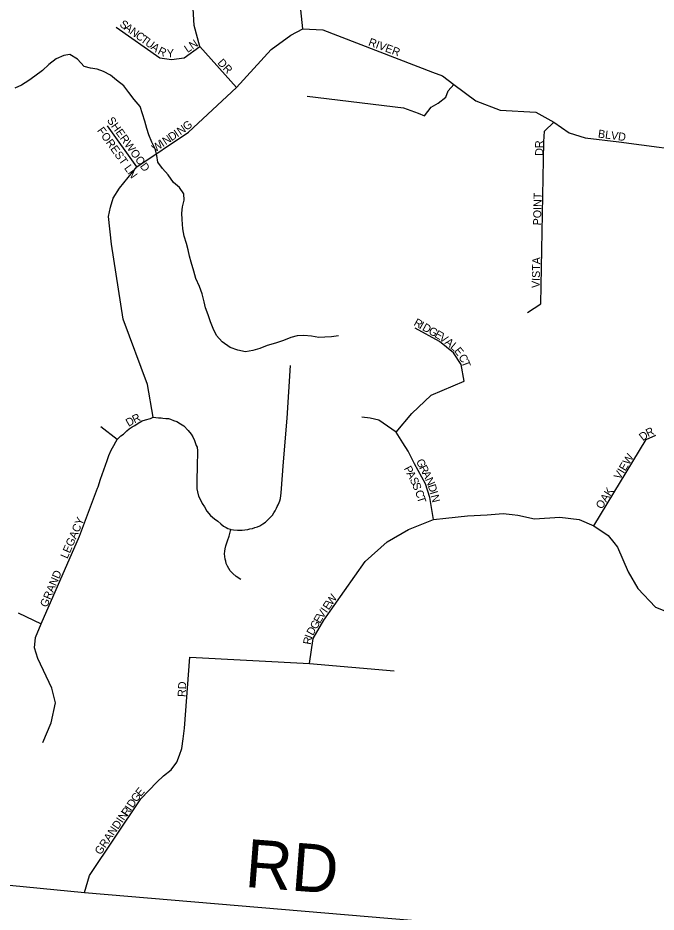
# Model space of a CAD drawing. Extents: x 0 to 1064, y 0 to 440.
# Drawn here: x 216.94 to 229.03, y 141.96 to 158.89 of the extents above; entities that cross this region are included whole.
import ezdxf

# ---------------------------------------------------------------- set-up
doc = ezdxf.new("R2010")
doc.units = 0
for name, color, linetype in [('GM_X_County_Road', 7, 'Continuous'), ('GM_X_County_Road_Text', 7, 'Continuous'), ('GM_X_Minor_River', 7, 'Continuous'), ('GM_X_Township_Road', 7, 'Continuous'), ('GM_X_Township_Subdivision', 7, 'Continuous'), ('GM_X_Township_Subdivision_Text', 7, 'Continuous')]:
    doc.layers.add(name, color=color, linetype=linetype)

msp = doc.modelspace()

# ---------------------------------------------------------------- linework, layer by layer
at = {"layer": 'GM_X_County_Road'}
msp.add_lwpolyline([(210.856, 148.164), (210.902, 148.053), (210.988, 147.945), (211.134, 147.956), (211.385, 148.01), (211.572, 148.026), (211.72, 147.948), (211.782, 147.854), (211.981, 147.333), (212.54, 145.964), (212.819, 145.507), (213.028, 145.15), (213.216, 144.884), (213.897, 144.447), (214.107, 144.144), (215.283, 143.149), (215.934, 142.551), (218.2, 142.332), (231.034, 141.244)], dxfattribs=at)
at = {"layer": 'GM_X_Minor_River'}
msp.add_lwpolyline([(223.009, 152.875), (222.881, 152.852), (222.754, 152.848), (222.638, 152.844), (222.499, 152.864), (222.353, 152.879), (222.231, 152.875), (222.109, 152.84), (221.968, 152.788), (221.816, 152.736), (221.663, 152.689), (221.522, 152.631), (221.388, 152.597), (221.253, 152.568), (221.108, 152.601), (220.957, 152.652), (220.807, 152.758), (220.699, 152.881), (220.641, 153.009), (220.588, 153.138), (220.542, 153.272), (220.495, 153.401), (220.467, 153.516), (220.427, 153.669), (220.381, 153.809), (220.31, 153.962), (220.27, 154.097), (220.224, 154.268), (220.19, 154.384), (220.167, 154.499), (220.133, 154.621), (220.087, 154.762), (220.065, 154.902), (220.049, 155.078), (220.045, 155.194), (220.059, 155.315), (220.086, 155.442), (220.082, 155.564), (219.999, 155.681), (219.885, 155.78), (219.784, 155.921), (219.677, 156.044), (219.593, 156.161), (219.571, 156.289), (219.537, 156.417), (219.478, 156.54), (219.42, 156.68), (219.379, 156.802), (219.345, 156.937), (219.299, 157.077), (219.253, 157.218), (219.139, 157.347), (219.038, 157.482), (218.943, 157.605), (218.805, 157.717), (218.691, 157.81), (218.558, 157.879), (218.438, 157.923), (218.316, 157.943), (218.195, 157.976), (218.07, 158.111), (217.926, 158.199), (217.81, 158.182), (217.663, 158.118), (217.527, 158.011), (217.404, 157.897), (217.262, 157.79), (217.145, 157.707), (217.01, 157.618), (216.881, 157.565)], dxfattribs=at)
at = {"layer": 'GM_X_Township_Road'}
for points in [[(224.643, 157.037), (224.766, 157.202), (224.898, 157.282), (225.047, 157.39), (225.087, 157.515), (225.199, 157.631)], [(222.417, 157.409), (224.24, 157.194), (224.52, 157.093), (224.643, 157.037)]]:
    msp.add_lwpolyline(points, dxfattribs=at)
at = {"layer": 'GM_X_Township_Subdivision'}
for points in [[(221.078, 157.575), (220.388, 158.353), (220.281, 158.753), (220.204, 160.043), (220.184, 160.66), (220.255, 160.969), (220.511, 161.551), (220.74, 161.966)], [(222.339, 158.685), (222.259, 159.415), (222.294, 160.086), (222.497, 160.677), (222.841, 161.172)], [(219.5, 151.332), (219.395, 151.952), (218.936, 153.186), (218.712, 154.611), (218.658, 155.134), (218.692, 155.311), (218.742, 155.483), (218.864, 155.67), (219.194, 156.072), (220.171, 156.733), (221.078, 157.575), (221.736, 158.298), (222.109, 158.57), (222.339, 158.685), (222.712, 158.671), (224.791, 157.868)], [(218.798, 158.717), (219.628, 158.135), (219.849, 158.108), (220.087, 158.135), (220.388, 158.353)], [(224.791, 157.868), (224.981, 157.795), (225.199, 157.631), (225.612, 157.321), (226.074, 157.149), (226.747, 157.106), (227.091, 156.922), (227.382, 156.72), (227.683, 156.624), (228.321, 156.544), (229.947, 156.331), (230.55, 156.371)], [(219.194, 156.072), (218.639, 156.851)], [(226.593, 153.314), (226.841, 153.482), (226.902, 156.546), (226.911, 156.749), (227.091, 156.922)], [(224.104, 151.049), (224.399, 151.402), (224.77, 151.748), (225.39, 152.017), (225.334, 152.332), (225.191, 152.551), (224.924, 152.765), (224.465, 153.018)], [(217.411, 145.169), (217.571, 145.542), (217.651, 145.925), (217.583, 146.2), (217.314, 146.761), (217.251, 146.962), (217.274, 147.162), (217.382, 147.42), (218.104, 149.08), (218.45, 149.991), (218.459, 150.016), (218.505, 150.158), (218.628, 150.514), (218.662, 150.609), (218.707, 150.705), (218.758, 150.797), (218.792, 150.865), (218.819, 150.912), (218.891, 150.982), (218.942, 151.012), (218.97, 151.04), (219.004, 151.077), (219.045, 151.111), (219.103, 151.152), (219.154, 151.176), (219.216, 151.217), (219.291, 151.262), (219.356, 151.282), (219.448, 151.31), (219.5, 151.332), (219.605, 151.323), (219.656, 151.323), (219.687, 151.316), (219.742, 151.31), (219.79, 151.306), (219.827, 151.293), (219.885, 151.272), (219.947, 151.251), (220.018, 151.207), (220.08, 151.166), (220.162, 151.081), (220.223, 151.012), (220.251, 150.961), (220.285, 150.893), (220.319, 150.797), (220.336, 150.766), (220.343, 150.695), (220.333, 150.391), (220.329, 150.145), (220.329, 150.126), (220.326, 150.046), (220.329, 149.974), (220.343, 149.919), (220.363, 149.837), (220.398, 149.769), (220.432, 149.701), (220.476, 149.632), (220.521, 149.554), (220.585, 149.472), (220.661, 149.41), (220.726, 149.362), (220.78, 149.311), (220.831, 149.27), (220.884, 149.245), (220.914, 149.226), (220.958, 149.21), (220.975, 149.206), (221.025, 149.197), (221.099, 149.193), (221.137, 149.193), (221.187, 149.195), (221.238, 149.199), (221.292, 149.203), (221.33, 149.218), (221.385, 149.226), (221.429, 149.241), (221.477, 149.256), (221.52, 149.277), (221.576, 149.313), (221.629, 149.346), (221.675, 149.388), (221.724, 149.441), (221.759, 149.479), (221.789, 149.521), (221.81, 149.561), (221.835, 149.611), (221.852, 149.641), (221.867, 149.67), (221.888, 149.714), (221.9, 149.748), (221.911, 149.79), (221.925, 149.899), (221.972, 150.486), (222.037, 151.317), (222.104, 152.309)], [(224.81, 149.395), (224.744, 149.809), (224.66, 150.07), (224.452, 150.449), (224.332, 150.691), (224.233, 150.848), (224.104, 151.049), (223.776, 151.275), (223.613, 151.311), (223.453, 151.334)], [(218.819, 150.912), (218.512, 151.153)], [(227.847, 149.275), (228.841, 150.908), (229.025, 150.994)], [(222.465, 146.665), (222.533, 147.141), (222.731, 147.489), (223.517, 148.599), (223.936, 148.975), (224.337, 149.204), (224.81, 149.395), (225.044, 149.42), (225.456, 149.466), (225.827, 149.481), (226.132, 149.511), (226.303, 149.489)], [(226.303, 149.489), (226.406, 149.476), (226.726, 149.41), (227.207, 149.438), (227.57, 149.395), (227.847, 149.275), (228.119, 149.095), (228.226, 148.96)], [(221.162, 148.259), (221.074, 148.316), (221.008, 148.373), (220.963, 148.425), (220.934, 148.47), (220.908, 148.51), (220.887, 148.565), (220.877, 148.605), (220.865, 148.641), (220.858, 148.693), (220.854, 148.743), (220.856, 148.795), (220.863, 148.84), (220.88, 148.897), (220.91, 148.989), (220.939, 149.081), (220.975, 149.206)], [(228.226, 148.96), (228.294, 148.874), (228.497, 148.401), (228.68, 148.086), (229.016, 147.735), (229.316, 147.613), (229.75, 147.543)], [(216.942, 147.626), (217.382, 147.42)], [(218.2, 142.332), (218.295, 142.651), (219.271, 144.104), (219.572, 144.424), (219.695, 144.538), (219.844, 144.656), (219.951, 144.798), (220.001, 144.935), (220.042, 145.058), (220.072, 145.241), (220.094, 145.441), (220.196, 146.789), (222.465, 146.665), (224.068, 146.531)]]:
    msp.add_lwpolyline(points, dxfattribs=at)

# ---------------------------------------------------------------- texts
at = {"layer": 'GM_X_County_Road_Text'}
msp.add_text('RD', height=0.9091, rotation=355.5623, dxfattribs=at).set_placement((221.224, 142.44))
at = {"layer": 'GM_X_Township_Subdivision_Text'}
for s, height, rotation, p in [('S', 0.152, 323.7858, (218.854, 158.746)), ('A', 0.152, 323.7814, (218.94, 158.683)), ('N', 0.152, 323.7988, (219.047, 158.604)), ('C', 0.152, 323.7905, (219.155, 158.525)), ('T', 0.152, 323.7858, (219.252, 158.454)), ('RIVER', 0.1515, 339.8316, (223.566, 158.377)), ('U', 0.152, 323.7814, (219.338, 158.391)), ('A', 0.152, 323.7988, (219.445, 158.313)), ('R', 0.152, 333.5313, (219.577, 158.219)), ('LN', 0.1515, 34.505, (220.153, 158.227)), ('Y', 0.152, 1.1196, (219.761, 158.148)), ('DR', 0.1515, 312.8801, (220.71, 158.036)), ('SHERWOOD', 0.1515, 305.7079, (218.619, 156.953)), ('FOREST LN', 0.1515, 305.6292, (218.434, 156.761)), ('N', 0.152, 34.5208, (220.017, 156.668)), ('G', 0.152, 39.3922, (220.138, 156.752)), ('N', 0.152, 34.0053, (219.739, 156.481)), ('D', 0.152, 34.0209, (219.85, 156.556)), ('I', 0.152, 33.9931, (219.96, 156.63)), ('BLVD', 0.1515, 352.3079, (227.92, 156.631)), ('W', 0.152, 34.0072, (219.54, 156.347)), ('I', 0.152, 34.0464, (219.684, 156.444)), ('DR', 0.1515, 90, (226.888, 156.283)), ('POINT', 0.1515, 88.8773, (226.848, 154.964)), ('VISTA', 0.1515, 88.6036, (226.821, 153.777)), ('R', 0.152, 330.5232, (224.424, 153.081)), ('I', 0.152, 330.4828, (224.528, 153.022)), ('D', 0.152, 330.4943, (224.586, 152.989)), ('G', 0.152, 330.5095, (224.702, 152.924)), ('E', 0.152, 330.184, (224.818, 152.858)), ('V', 0.152, 324.6732, (224.907, 152.807)), ('A', 0.152, 321.1627, (225.014, 152.732)), ('L', 0.152, 319.3128, (225.117, 152.649)), ('E', 0.152, 308.6897, (225.193, 152.585)), ('C', 0.152, 300.4557, (225.278, 152.473)), ('T', 0.152, 290.7767, (225.336, 152.375)), ('R', 0.152, 26.2067, (219.149, 151.212)), ('D', 0.152, 29.6554, (219.035, 151.148)), ('D', 0.152, 38.0111, (228.777, 150.876)), ('R', 0.152, 24.7836, (228.874, 150.954)), ('VIEW', 0.1515, 59.0386, (228.345, 150.138)), ('P', 0.152, 298.0436, (224.245, 150.361)), ('G', 0.152, 297.22, (224.475, 150.496)), ('R', 0.152, 297.2167, (224.536, 150.378)), ('A', 0.152, 297.6404, (224.295, 150.267)), ('A', 0.152, 297.2006, (224.591, 150.271)), ('S', 0.152, 296.0764, (224.356, 150.15)), ('S', 0.152, 292.8721, (224.402, 150.056)), ('N', 0.152, 293.2589, (224.651, 150.155)), ('D', 0.152, 287.0802, (224.702, 150.037)), ('C', 0.152, 289.1032, (224.458, 149.923)), ('I', 0.152, 286.2637, (224.741, 149.91)), ('OAK', 0.1515, 57.3842, (227.999, 149.579)), ('T', 0.152, 287.0786, (224.496, 149.811)), ('N', 0.152, 283.8136, (224.759, 149.847)), ('LEGACY', 0.1515, 66.6699, (217.877, 148.642)), ('GRAND', 0.1515, 67.1093, (217.49, 147.721)), ('E', 0.152, 55.1199, (222.825, 147.67)), ('W', 0.152, 55.124, (222.886, 147.757)), ('V', 0.152, 55.8067, (222.712, 147.505)), ('I', 0.152, 55.1583, (222.787, 147.615)), ('E', 0.152, 58.8113, (222.658, 147.416)), ('D', 0.152, 60.6184, (222.527, 147.185)), ('G', 0.152, 59.9434, (222.592, 147.301)), ('R', 0.152, 80.2382, (222.488, 147.017)), ('I', 0.152, 69.6844, (222.506, 147.128)), ('RD', 0.1515, 86.989, (220.115, 146.031)), ('E', 0.152, 49.953, (219.265, 144.137)), ('G', 0.152, 54.6122, (219.19, 144.031)), ('R', 0.152, 56.2358, (219.013, 143.766)), ('I', 0.152, 56.2511, (219.079, 143.865)), ('D', 0.152, 56.2311, (219.116, 143.921)), ('GRANDIN', 0.1515, 55.8104, (218.506, 143.033))]:
    msp.add_text(s, height=height, rotation=rotation, dxfattribs=at).set_placement(p)

doc.saveas('drawing.dxf')
